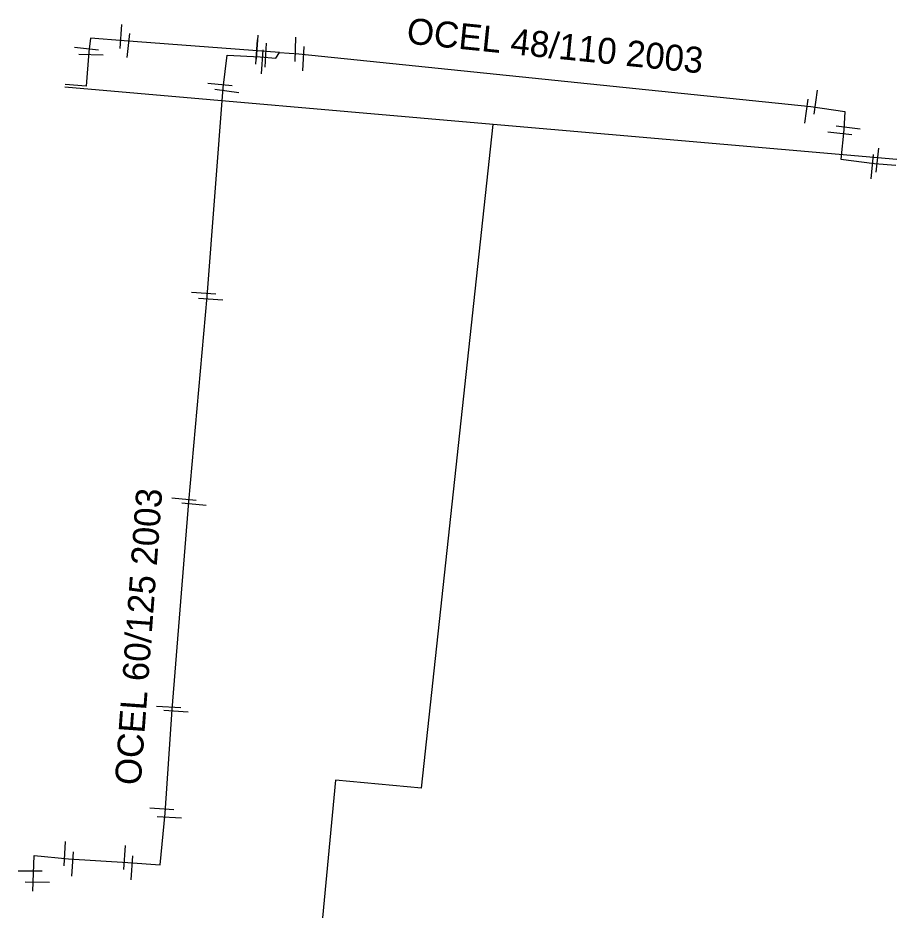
# Model space of a CAD drawing. Extents: x -642943 to -623314, y -1138561 to -1113539.
# Drawn here: x -642552.54 to -642527.17, y -1114236.69 to -1114210.7 of the extents above; entities that cross this region are included whole.
import ezdxf

# ---------------------------------------------------------------- set-up
doc = ezdxf.new("R2010")
doc.units = 0
for name, color, linetype in [('horkovod dimenze', 7, 'Continuous'), ('horkovod předisol', 7, 'Continuous'), ('horkovod sváry', 7, 'Continuous'), ('horkovod trasa', 7, 'Continuous'), ('horkovod zrušený', 7, 'Continuous')]:
    doc.layers.add(name, color=color, linetype=linetype)

# ---------------------------------------------------------------- blocks, each defined once
blk = doc.blocks.new('SPH')
at = {"layer": 'horkovod sváry'}
blk.add_line((0, -0.035), (0, 0.035), dxfattribs=at)

msp = doc.modelspace()

# ---------------------------------------------------------------- linework, layer by layer
at = {"layer": 'horkovod předisol'}
for points in [[(-642544.988, -1114211.694), (-642549.474, -1114211.358), (-642550.451, -1114211.282), (-642550.497, -1114211.674), (-642550.577, -1114212.665), (-642551.179, -1114212.612)], [(-642552.114, -1114235.911), (-642552.072, -1114234.881), (-642551.079, -1114234.978), (-642549.368, -1114235.09), (-642548.441, -1114235.151), (-642548.289, -1114233.661), (-642548.091, -1114230.665), (-642547.608, -1114224.672), (-642547.084, -1114218.735), (-642546.616, -1114212.712), (-642546.5, -1114211.773), (-642545.553, -1114211.822), (-642545.1, -1114211.857), (-642544.988, -1114211.694)], [(-642544.988, -1114211.694), (-642544.434, -1114211.729), (-642529.653, -1114213.256), (-642528.67, -1114213.393), (-642528.706, -1114213.928), (-642528.792, -1114214.773), (-642527.82, -1114214.895), (-642527.203, -1114214.951)]]:
    msp.add_lwpolyline(points, dxfattribs=at)
at = {"layer": 'horkovod trasa'}
for points in [[(-642544.988, -1114211.694), (-642549.474, -1114211.358), (-642550.451, -1114211.282), (-642550.497, -1114211.674), (-642550.577, -1114212.665), (-642551.179, -1114212.612)], [(-642552.114, -1114235.911), (-642552.072, -1114234.881), (-642551.079, -1114234.978), (-642549.368, -1114235.09), (-642548.441, -1114235.151), (-642548.289, -1114233.661), (-642548.091, -1114230.665), (-642547.608, -1114224.672), (-642547.084, -1114218.735), (-642546.616, -1114212.712), (-642546.5, -1114211.773), (-642545.553, -1114211.822), (-642545.1, -1114211.857), (-642544.988, -1114211.694)], [(-642544.988, -1114211.694), (-642544.434, -1114211.729), (-642529.653, -1114213.256), (-642528.67, -1114213.393), (-642528.706, -1114213.928), (-642528.792, -1114214.773), (-642527.82, -1114214.895), (-642527.203, -1114214.951)]]:
    msp.add_lwpolyline(points, dxfattribs=at)
at = {"layer": 'horkovod zrušený'}
for p, q in [((-642538.823, -1114213.771), (-642551.187, -1114212.695)), ((-642540.89, -1114232.935), (-642538.823, -1114213.771)), ((-642527.167, -1114214.785), (-642538.823, -1114213.771)), ((-642543.379, -1114232.706), (-642543.746, -1114236.689)), ((-642540.89, -1114232.935), (-642543.379, -1114232.706))]:
    msp.add_line(p, q, dxfattribs=at)

# ---------------------------------------------------------------- block references
at = {"layer": 'horkovod sváry'}
for p, xscale, yscale, rotation in [((-642549.58, -1114211.23), 9.999994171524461, 9.999994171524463, 176.05484130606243), ((-642549.36, -1114211.49), 9.999984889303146, 9.999984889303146, 173.44310224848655), ((-642545.63, -1114211.54), 9.999998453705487, 9.999998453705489, -4.315912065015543), ((-642544.54, -1114211.6), 9.999992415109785, 9.999992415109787, 177.95450580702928), ((-642550.56, -1114211.58), 10.000011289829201, 10.000011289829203, -96.48303151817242), ((-642545.66, -1114211.68), 10.000017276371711, 10.00001727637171, 175.50213112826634), ((-642545.39, -1114211.77), 10.000009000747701, 10.000009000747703, -3.2396651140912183), ((-642544.31, -1114211.87), 10.000015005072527, 10.00001500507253, 176.50536513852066), ((-642550.43, -1114211.75), 9.999981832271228, 9.999981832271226, -91.88825540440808), ((-642545.49, -1114211.96), 9.999998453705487, 9.999998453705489, -4.315912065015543), ((-642546.71, -1114212.62), 9.999988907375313, 9.999988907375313, 84.42780219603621), ((-642546.51, -1114212.81), 9.999996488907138, 9.99999648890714, 81.46918161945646), ((-642529.51, -1114213.13), 9.999998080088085, 9.999998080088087, -8.498443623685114), ((-642529.78, -1114213.39), 9.999977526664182, 9.99997752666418, -7.537360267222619), ((-642528.58, -1114213.85), 10.000013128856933, 10.000013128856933, -97.124950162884), ((-642528.82, -1114214.02), 10.000009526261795, 10.000009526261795, -95.9223938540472), ((-642527.89, -1114214.99), 9.99999474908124, 9.99999474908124, 174.09395955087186), ((-642527.74, -1114214.8), 10.000003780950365, 10.000003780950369, 173.3332609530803), ((-642547.18, -1114218.65), 9.999992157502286, 9.999992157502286, 86.1254413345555), ((-642546.98, -1114218.82), 9.999989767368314, 9.999989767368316, 86.19336141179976), ((-642547.75, -1114224.6), 9.999985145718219, 9.999985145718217, 84.53903944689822), ((-642547.46, -1114224.74), 10.00000787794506, 10.00000787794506, 84.7930827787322), ((-642548.19, -1114230.6), 9.999984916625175, 9.999984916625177, 86.09067368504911), ((-642547.98, -1114230.72), 9.999995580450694, 9.999995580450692, 85.65251353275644), ((-642548.39, -1114233.54), 9.999990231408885, 9.999990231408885, 86.4989411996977), ((-642548.17, -1114233.79), 9.999996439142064, 9.999996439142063, 86.88191410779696), ((-642551.19, -1114234.83), 9.99999208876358, 9.99999208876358, -3.6593155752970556), ((-642549.47, -1114234.94), 9.99999208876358, 9.999992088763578, 176.34068442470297), ((-642550.96, -1114235.13), 10.000005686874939, 10.000005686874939, -3.7020875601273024), ((-642549.26, -1114235.24), 10.000005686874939, 10.000005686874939, 176.2979124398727), ((-642552.19, -1114235.34), 10, 10, 90), ((-642551.98, -1114235.66), 9.999980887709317, 9.999980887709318, 88.78114179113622)]:
    msp.add_blockref('SPH', p, dxfattribs=dict(at, xscale=xscale, yscale=yscale, rotation=rotation))

# ---------------------------------------------------------------- texts
at = {"layer": 'horkovod dimenze'}
for s, height, rotation, p in [('OCEL 48/110 2003', 0.75, 354.1875, (-642541.343, -1114211.43)), ('OCEL 60/125 2003', 0.74999, 85.8058, (-642549.001, -1114232.871))]:
    msp.add_text(s, height=height, rotation=rotation, dxfattribs=at).set_placement(p)

doc.saveas('drawing.dxf')
